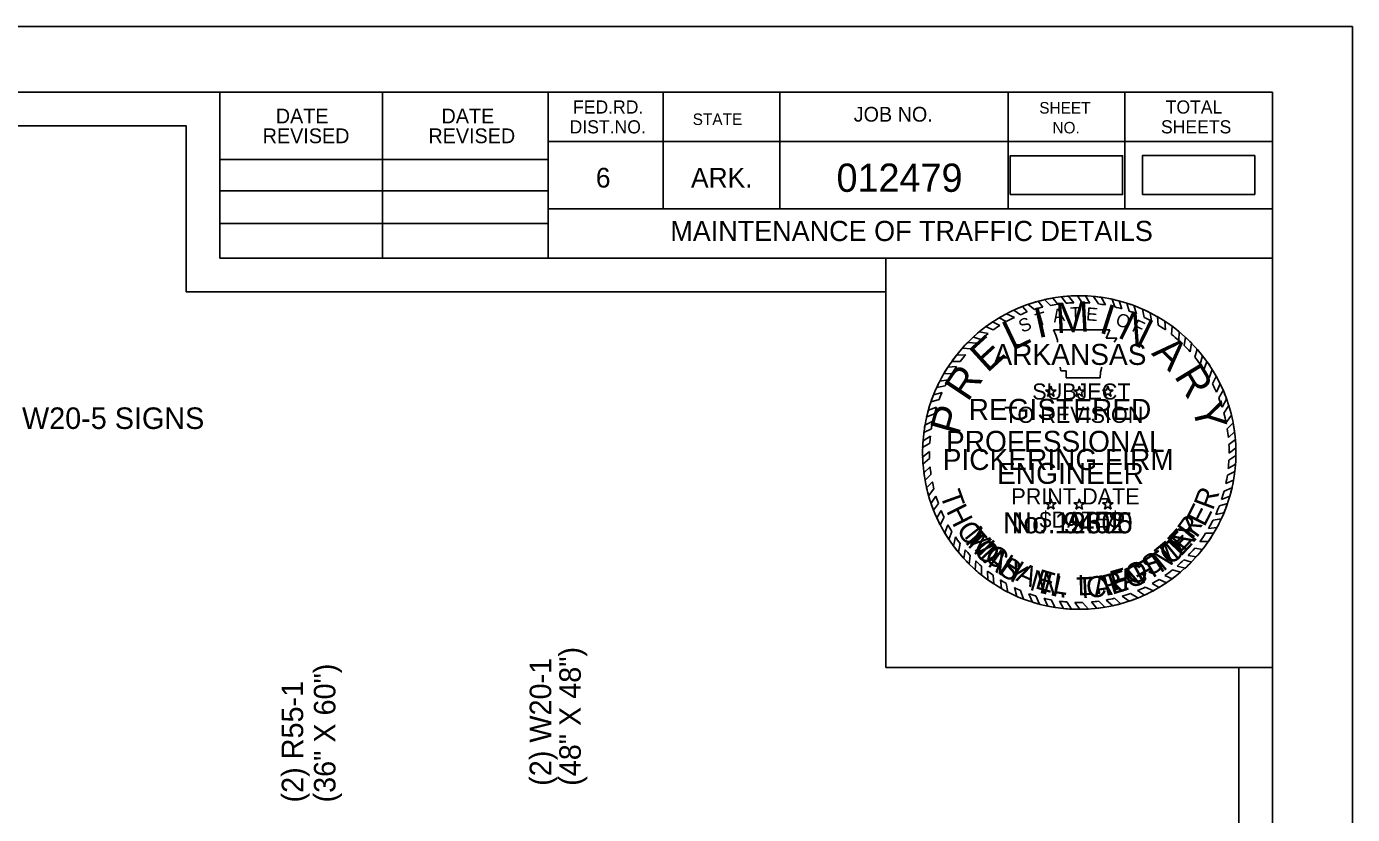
# Model space of a CAD drawing. Extents: x 1373222 to 1374279, y 380783 to 380996.
# Drawn here: x 1373476.4 to 1373555.3, y 380949.6 to 380996.5 of the extents above; entities that cross this region are included whole.
import ezdxf

# ---------------------------------------------------------------- set-up
doc = ezdxf.new("R2010")
doc.units = 0
for name, color, linetype in [('Default', 7, 'Continuous'), ('R_Border', 7, 'Continuous'), ('R_Border Notes', 7, 'Continuous'), ('R_Draft', 7, 'Continuous'), ('R_No Plot', 7, 'Continuous'), ('STAMP_PE_CRAFTON', 7, 'Continuous'), ('STAMP_PE_FOSTER', 7, 'Continuous'), ('STAMP_PE_SEAL-INFO', 7, 'Continuous'), ('STAMP_PE_TAEGTMEYER', 7, 'Continuous'), ('STAMP_PE_TXT', 7, 'Continuous'), ('STAMP_PRELIMINARY', 7, 'Continuous')]:
    doc.layers.add(name, color=color, linetype=linetype)

msp = doc.modelspace()

# ---------------------------------------------------------------- linework, layer by layer
at = {"layer": 'Default'}
for points in [[(1373534.953, 380986.497), (1373541.636, 380986.497), (1373541.636, 380988.808), (1373534.953, 380988.808)], [(1373542.823, 380986.507), (1373549.506, 380986.507), (1373549.506, 380988.818), (1373542.823, 380988.818)]]:
    msp.add_lwpolyline(points, close=True, dxfattribs=at)
at = {"layer": 'R_Border'}
for p, q in [((1373234.384, 380992.592), (1373550.564, 380992.592)), ((1373487.924, 380982.712), (1373487.924, 380992.592)), ((1373497.604, 380982.712), (1373497.604, 380992.592)), ((1373507.464, 380992.592), (1373507.464, 380982.712)), ((1373514.304, 380992.592), (1373514.304, 380985.652)), ((1373521.244, 380992.592), (1373521.244, 380985.652)), ((1373534.824, 380992.592), (1373534.824, 380985.652)), ((1373541.764, 380992.592), (1373541.764, 380985.652)), ((1373550.564, 380787.132), (1373550.564, 380992.592)), ((1373550.564, 380989.652), (1373507.464, 380989.652)), ((1373550.564, 380989.672), (1373550.564, 380989.672)), ((1373487.924, 380988.572), (1373507.464, 380988.572)), ((1373487.924, 380986.712), (1373507.464, 380986.712)), ((1373550.564, 380985.652), (1373507.464, 380985.652)), ((1373510.424, 380985.652), (1373550.564, 380985.652)), ((1373487.924, 380984.772), (1373507.464, 380984.772)), ((1373550.564, 380982.712), (1373487.924, 380982.712))]:
    msp.add_line(p, q, dxfattribs=at)
at = {"layer": 'R_No Plot'}
for points in [[(1373221.977, 380996.487), (1373555.317, 380996.487), (1373555.317, 380783.15), (1373221.977, 380783.15)], [(1373548.564, 380891.862), (1373236.384, 380891.862), (1373236.384, 380990.592), (1373485.924, 380990.592), (1373485.924, 380980.712), (1373503.464, 380980.712), (1373527.564, 380980.712), (1373527.564, 380958.38), (1373548.564, 380958.38)], [(1373236.384, 380990.592), (1373485.924, 380990.592), (1373485.924, 380980.712), (1373503.464, 380980.712), (1373527.564, 380980.712), (1373527.564, 380958.38), (1373548.564, 380958.38), (1373548.564, 380789.132), (1373236.384, 380789.132)], [(1373527.564, 380982.712), (1373550.564, 380982.712), (1373550.564, 380958.38), (1373527.564, 380958.38)]]:
    msp.add_lwpolyline(points, close=True, dxfattribs=at)
at = {"layer": 'STAMP_PE_SEAL-INFO'}
for p, q in [((1373537.485, 380980.343), (1373537.784, 380979.976)), ((1373538.001, 380980.417), (1373538.282, 380980.034)), ((1373538.736, 380980.062), (1373538.424, 380980.456)), ((1373539.234, 380980.067), (1373538.955, 380980.477)), ((1373539.692, 380980.046), (1373539.434, 380980.47)), ((1373540.198, 380979.996), (1373539.906, 380980.44)), ((1373540.624, 380979.931), (1373540.366, 380980.386)), ((1373535.168, 380979.625), (1373535.558, 380979.35)), ((1373535.676, 380979.84), (1373535.971, 380979.514)), ((1373536.024, 380979.968), (1373536.405, 380979.662)), ((1373536.615, 380980.15), (1373536.903, 380979.802)), ((1373537.003, 380980.247), (1373537.359, 380979.904)), ((1373541.186, 380979.812), (1373541.012, 380980.272)), ((1373541.587, 380979.704), (1373541.428, 380980.173)), ((1373542.039, 380979.557), (1373541.898, 380980.037)), ((1373542.458, 380979.397), (1373542.313, 380979.893)), ((1373542.919, 380979.192), (1373542.816, 380979.69)), ((1373533.903, 380978.918), (1373534.344, 380978.716)), ((1373534.289, 380979.162), (1373534.722, 380978.939)), ((1373534.737, 380979.413), (1373535.201, 380979.188)), ((1373543.365, 380978.963), (1373543.278, 380979.471)), ((1373543.752, 380978.736), (1373543.713, 380979.236)), ((1373544.187, 380978.45), (1373544.156, 380978.965)), ((1373532.762, 380978.024), (1373533.22, 380977.885)), ((1373533.105, 380978.324), (1373533.635, 380978.224)), ((1373533.482, 380978.652), (1373533.938, 380978.447)), ((1373537.537, 380978.446), (1373540.882, 380978.446)), ((1373537.659, 380978.139), (1373537.537, 380978.446)), ((1373537.763, 380977.841), (1373537.659, 380978.139)), ((1373540.882, 380978.446), (1373540.657, 380977.954)), ((1373544.547, 380978.183), (1373544.582, 380978.67)), ((1373544.994, 380977.81), (1373545.013, 380978.333)), ((1373545.306, 380977.518), (1373545.376, 380978.017)), ((1373532.103, 380977.356), (1373532.625, 380977.318)), ((1373532.426, 380977.701), (1373532.97, 380977.66)), ((1373537.77, 380977.727), (1373537.763, 380977.841)), ((1373540.657, 380977.954), (1373541.289, 380977.954)), ((1373541.289, 380977.954), (1373541.144, 380977.727)), ((1373545.665, 380977.145), (1373545.732, 380977.671)), ((1373545.939, 380976.828), (1373546.076, 380977.3)), ((1373531.48, 380976.576), (1373531.985, 380976.57)), ((1373531.758, 380976.945), (1373532.307, 380976.967)), ((1373546.263, 380976.411), (1373546.398, 380976.911)), ((1373546.483, 380976.096), (1373546.661, 380976.559)), ((1373530.999, 380975.831), (1373531.488, 380975.851)), ((1373531.245, 380976.232), (1373531.761, 380976.265)), ((1373537.961, 380976.018), (1373537.935, 380976.235)), ((1373538.275, 380976.018), (1373537.961, 380976.018)), ((1373538.275, 380975.588), (1373538.275, 380976.018)), ((1373540.321, 380975.926), (1373540.305, 380975.588)), ((1373540.399, 380976.235), (1373540.321, 380975.926)), ((1373546.791, 380975.599), (1373546.974, 380976.09)), ((1373546.991, 380975.232), (1373547.217, 380975.677)), ((1373530.58, 380975.018), (1373531.082, 380975.122)), ((1373530.768, 380975.407), (1373531.266, 380975.472)), ((1373540.305, 380975.588), (1373538.275, 380975.588)), ((1373547.222, 380974.748), (1373547.448, 380975.233)), ((1373547.362, 380974.411), (1373547.626, 380974.845)), ((1373530.246, 380974.179), (1373530.73, 380974.316)), ((1373530.396, 380974.586), (1373530.9, 380974.732)), ((1373547.557, 380973.862), (1373547.827, 380974.336)), ((1373529.985, 380973.269), (1373530.455, 380973.462)), ((1373530.089, 380973.677), (1373530.567, 380973.845)), ((1373547.665, 380973.497), (1373547.958, 380973.95)), ((1373547.798, 380972.939), (1373548.116, 380973.385)), ((1373530.263, 380972.564), (1373529.818, 380972.342)), ((1373530.349, 380973.023), (1373529.883, 380972.774)), ((1373547.867, 380972.559), (1373548.22, 380972.912)), ((1373530.168, 380971.703), (1373529.746, 380971.447)), ((1373530.204, 380972.128), (1373529.768, 380971.847)), ((1373547.933, 380972.05), (1373548.306, 380972.386)), ((1373547.965, 380971.631), (1373548.355, 380971.923)), ((1373530.151, 380971.21), (1373529.746, 380970.874)), ((1373547.967, 380970.708), (1373548.386, 380970.985)), ((1373547.978, 380971.113), (1373548.383, 380971.435)), ((1373530.158, 380970.803), (1373529.766, 380970.478)), ((1373530.191, 380970.308), (1373529.82, 380969.951)), ((1373547.927, 380970.202), (1373548.361, 380970.459)), ((1373530.243, 380969.878), (1373529.889, 380969.505)), ((1373530.322, 380969.42), (1373529.982, 380969.052)), ((1373547.786, 380969.314), (1373548.241, 380969.509)), ((1373547.876, 380969.813), (1373548.319, 380970.033)), ((1373530.415, 380969.001), (1373530.103, 380968.586)), ((1373530.539, 380968.554), (1373530.244, 380968.136)), ((1373547.531, 380968.368), (1373548.021, 380968.569)), ((1373547.678, 380968.862), (1373548.149, 380969.063)), ((1373530.68, 380968.131), (1373530.398, 380967.719)), ((1373547.396, 380967.988), (1373547.879, 380968.119)), ((1373530.846, 380967.704), (1373530.584, 380967.282)), ((1373531.018, 380967.321), (1373530.79, 380966.86)), ((1373547.021, 380967.137), (1373547.509, 380967.205)), ((1373547.182, 380967.473), (1373547.67, 380967.57)), ((1373531.253, 380966.862), (1373531.062, 380966.373)), ((1373531.488, 380966.459), (1373531.305, 380965.988)), ((1373531.691, 380966.147), (1373531.581, 380965.595)), ((1373546.577, 380966.358), (1373547.054, 380966.352)), ((1373546.749, 380966.638), (1373547.25, 380966.693)), ((1373531.972, 380965.757), (1373531.87, 380965.226)), ((1373532.276, 380965.379), (1373532.189, 380964.859)), ((1373545.93, 380965.47), (1373546.391, 380965.39)), ((1373546.238, 380965.864), (1373546.742, 380965.867)), ((1373532.578, 380965.041), (1373532.516, 380964.519)), ((1373532.901, 380964.716), (1373532.871, 380964.187)), ((1373545.292, 380964.777), (1373545.732, 380964.64)), ((1373545.546, 380965.037), (1373546.023, 380964.951)), ((1373533.245, 380964.403), (1373533.242, 380963.874)), ((1373533.605, 380964.109), (1373533.624, 380963.585)), ((1373533.943, 380963.859), (1373533.979, 380963.341)), ((1373544.154, 380963.838), (1373544.593, 380963.649)), ((1373544.615, 380964.181), (1373545.083, 380964.035)), ((1373544.886, 380964.405), (1373545.357, 380964.276)), ((1373534.37, 380963.578), (1373534.431, 380963.065)), ((1373534.721, 380963.372), (1373534.812, 380962.859)), ((1373535.202, 380963.122), (1373535.358, 380962.601)), ((1373542.988, 380963.152), (1373543.472, 380962.94)), ((1373543.396, 380963.365), (1373543.813, 380963.132)), ((1373543.811, 380963.61), (1373544.26, 380963.414)), ((1373535.574, 380962.953), (1373535.747, 380962.442)), ((1373536.067, 380962.761), (1373536.276, 380962.259)), ((1373536.476, 380962.625), (1373536.703, 380962.136)), ((1373536.984, 380962.488), (1373537.197, 380962.021)), ((1373537.382, 380962.402), (1373537.629, 380961.944)), ((1373537.882, 380962.32), (1373538.122, 380961.88)), ((1373538.319, 380962.273), (1373538.593, 380961.844)), ((1373538.803, 380962.245), (1373539.106, 380961.832)), ((1373539.263, 380962.244), (1373539.607, 380961.848)), ((1373539.782, 380962.27), (1373540.108, 380961.891)), ((1373540.22, 380962.317), (1373540.593, 380961.958)), ((1373540.665, 380962.386), (1373541.054, 380962.047)), ((1373541.158, 380962.491), (1373541.535, 380962.166)), ((1373541.617, 380962.615), (1373542.034, 380962.318)), ((1373542.11, 380962.778), (1373542.553, 380962.51)), ((1373542.529, 380962.942), (1373542.952, 380962.682))]:
    msp.add_line(p, q, dxfattribs=at)
for radius, start, end in [(9.323, 99.75254, 102.77648), (9.323, 93.93815, 96.55172), (9.323, 87.72979, 90.67067), (9.323, 81.97315, 84.82355), (9.323, 111.31242, 114.70259), (9.323, 105.23389, 109.03519), (8.914, 104.03521, 107.36155), (8.914, 98.25799, 101.03289), (8.914, 92.11016, 95.03666), (8.914, 85.96279, 88.9097), (8.914, 79.92642, 82.69597), (9.323, 75.31251, 77.94263), (8.914, 73.55748, 76.23144), (9.323, 69.60611, 72.30577), (8.914, 67.62483, 70.50398), (9.323, 63.13288, 66.2704), (9.323, 123.61993, 126.59063), (9.323, 117.65441, 120.80988), (8.914, 115.68692, 119.15827), (8.914, 110.30864, 113.16588), (8.914, 61.15575, 64.37837), (9.323, 56.90029, 60.09423), (9.323, 129.73259, 132.53764), (8.914, 127.52969, 130.96829), (8.914, 121.97456, 125.11001), (8.914, 54.92383, 58.27016), (8.914, 48.30163, 52.03953), (9.323, 50.3492, 53.71593), (9.323, 44.3405, 47.39292), (9.323, 135.40208, 138.30314), (8.914, 133.13306, 136.25623), (8.914, 42.22116, 45.55119), (9.323, 38.12472, 41.23157), (9.323, 141.60556, 144.44865), (8.914, 139.30101, 142.58729), (8.914, 36.13503, 39.53106), (9.323, 31.96138, 35.42937), (9.323, 147.00719, 149.89904), (8.914, 145.01972, 148.21036), (8.914, 29.90321, 33.66454), (9.323, 25.93909, 29.01247), (9.323, 152.86398, 155.51889), (8.914, 151.03153, 153.57304), (8.914, 23.77322, 27.22114), (9.323, 19.95381, 23.31409), (9.323, 158.40766, 161.07015), (8.914, 156.34018, 159.23194), (8.914, 17.68022, 21.42509), (9.323, 164.3068, 166.89395), (8.914, 162.43309, 165.00133), (8.914, 11.54445, 15.23639), (9.323, 13.84205, 17.44468), (9.323, 170.0003, 172.68778), (8.914, 167.90481, 170.90393), (8.914, 5.7599, 9.06056), (9.323, 7.58519, 10.86211), (9.323, 175.74093, 178.2066), (8.914, 173.73, 176.47337), (9.323, 1.72155, 4.72681), (9.323, 181.72508, 184.16255), (8.914, 179.64537, 182.26333), (8.914, 359.73289, 3.06392), (9.323, 355.71562, 358.95694), (8.914, 185.45389, 188.23401), (8.914, 353.86319, 357.12742), (9.323, 187.42037, 190.19271), (8.914, 191.22736, 193.98583), (8.914, 348.07782, 351.34355), (9.323, 349.83047, 353.08845), (9.323, 193.03695, 195.99732), (8.914, 196.96751, 199.83526), (8.914, 341.77699, 345.09248), (9.323, 343.89247, 347.03502), (9.323, 198.89671, 201.62812), (8.914, 335.6038, 339.18578), (9.323, 337.38367, 340.99332), (9.323, 204.54793, 207.43282), (8.914, 202.77613, 205.47915), (8.914, 329.55488, 333.20757), (9.323, 331.40371, 334.93315), (9.323, 210.86355, 213.65709), (8.914, 208.78826, 211.79343), (8.914, 214.18375, 217.27474), (8.914, 323.58513, 327.44069), (9.323, 325.44052, 328.98725), (9.323, 216.61154, 219.49098), (8.914, 220.39088, 223.30564), (8.914, 316.65308, 320.37109), (9.323, 318.28455, 321.80429), (9.323, 222.47995, 225.38008), (8.914, 226.24938, 229.24068), (8.914, 310.77436, 314.31605), (9.323, 312.45177, 315.66328), (9.323, 228.36648, 231.34802), (8.914, 232.22904, 234.93361), (8.914, 304.82299, 308.51428), (9.323, 306.37206, 310.20799), (9.323, 234.29502, 236.94517), (8.914, 238.22227, 240.83529), (9.323, 240.1977, 242.86128), (8.914, 244.32043, 246.94859), (8.914, 292.87452, 296.11851), (8.914, 299.07679, 302.17235), (9.323, 300.62101, 303.87026), (9.323, 246.57598, 249.15579), (8.914, 250.34912, 253.12157), (9.323, 252.59667, 255.32518), (8.914, 256.50505, 259.11916), (8.914, 262.37828, 265.20115), (8.914, 268.3215, 271.27698), (8.914, 274.61565, 277.44863), (8.914, 280.34588, 283.58137), (8.914, 286.64233, 289.97826), (9.323, 288.57086, 291.97334), (9.323, 294.64808, 298.21662), (9.323, 258.44328, 261.13983), (9.323, 264.19784, 267.10092), (9.323, 270.25484, 273.33609), (9.323, 276.42389, 279.43574), (9.323, 282.31994, 285.37019)]:
    msp.add_arc((1373539.064, 380971.155), radius, start, end, dxfattribs=at)
at = {"layer": 'STAMP_PE_TXT'}
for p, q in [((1373537.244, 380974.726), (1373537.046, 380974.871)), ((1373537.046, 380974.871), (1373537.291, 380974.871)), ((1373537.291, 380974.871), (1373537.366, 380975.104)), ((1373537.366, 380975.104), (1373537.442, 380974.871)), ((1373537.442, 380974.871), (1373537.687, 380974.871)), ((1373537.687, 380974.871), (1373537.489, 380974.726)), ((1373538.942, 380974.726), (1373538.743, 380974.871)), ((1373538.743, 380974.871), (1373538.989, 380974.871)), ((1373538.989, 380974.871), (1373539.064, 380975.104)), ((1373539.064, 380975.104), (1373539.14, 380974.871)), ((1373539.14, 380974.871), (1373539.385, 380974.871)), ((1373539.385, 380974.871), (1373539.187, 380974.726)), ((1373540.64, 380974.726), (1373540.441, 380974.871)), ((1373540.441, 380974.871), (1373540.687, 380974.871)), ((1373540.687, 380974.871), (1373540.762, 380975.104)), ((1373540.762, 380975.104), (1373540.838, 380974.871)), ((1373540.838, 380974.871), (1373541.083, 380974.871)), ((1373541.083, 380974.871), (1373540.885, 380974.726)), ((1373537.168, 380974.493), (1373537.244, 380974.726)), ((1373537.366, 380974.637), (1373537.168, 380974.493)), ((1373537.565, 380974.493), (1373537.366, 380974.637)), ((1373537.489, 380974.726), (1373537.565, 380974.493)), ((1373538.866, 380974.493), (1373538.942, 380974.726)), ((1373539.064, 380974.637), (1373538.866, 380974.493)), ((1373539.263, 380974.493), (1373539.064, 380974.637)), ((1373539.187, 380974.726), (1373539.263, 380974.493)), ((1373540.564, 380974.493), (1373540.64, 380974.726)), ((1373540.762, 380974.637), (1373540.564, 380974.493)), ((1373540.961, 380974.493), (1373540.762, 380974.637)), ((1373540.885, 380974.726), (1373540.961, 380974.493)), ((1373537.244, 380968.019), (1373537.046, 380968.164)), ((1373537.046, 380968.164), (1373537.291, 380968.164)), ((1373537.168, 380967.786), (1373537.244, 380968.019)), ((1373537.366, 380967.93), (1373537.168, 380967.786)), ((1373537.291, 380968.164), (1373537.366, 380968.397)), ((1373537.366, 380968.397), (1373537.442, 380968.164)), ((1373537.565, 380967.786), (1373537.366, 380967.93)), ((1373537.442, 380968.164), (1373537.687, 380968.164)), ((1373537.687, 380968.164), (1373537.489, 380968.019)), ((1373537.489, 380968.019), (1373537.565, 380967.786)), ((1373538.942, 380968.019), (1373538.743, 380968.164)), ((1373538.743, 380968.164), (1373538.989, 380968.164)), ((1373538.866, 380967.786), (1373538.942, 380968.019)), ((1373539.064, 380967.93), (1373538.866, 380967.786)), ((1373538.989, 380968.164), (1373539.064, 380968.397)), ((1373539.064, 380968.397), (1373539.14, 380968.164)), ((1373539.263, 380967.786), (1373539.064, 380967.93)), ((1373539.14, 380968.164), (1373539.385, 380968.164)), ((1373539.385, 380968.164), (1373539.187, 380968.019)), ((1373539.187, 380968.019), (1373539.263, 380967.786)), ((1373540.64, 380968.019), (1373540.441, 380968.164)), ((1373540.441, 380968.164), (1373540.687, 380968.164)), ((1373540.564, 380967.786), (1373540.64, 380968.019)), ((1373540.762, 380967.93), (1373540.564, 380967.786)), ((1373540.687, 380968.164), (1373540.762, 380968.397)), ((1373540.762, 380968.397), (1373540.838, 380968.164)), ((1373540.961, 380967.786), (1373540.762, 380967.93)), ((1373540.838, 380968.164), (1373541.083, 380968.164)), ((1373541.083, 380968.164), (1373540.885, 380968.019)), ((1373540.885, 380968.019), (1373540.961, 380967.786))]:
    msp.add_line(p, q, dxfattribs=at)
at = {"layer": 'STAMP_PRELIMINARY'}
msp.add_circle((1373539.064, 380971.155), 9.323, dxfattribs=at)

# ---------------------------------------------------------------- texts
at = {"layer": 'R_Border'}
for s, height, p in [('DATE', 0.8792, (1373491.262, 380990.729)), ('DATE', 0.8792, (1373501.122, 380990.729)), ('FED.RD.', 0.7819, (1373508.944, 380991.312)), ('JOB NO.', 0.8792, (1373525.644, 380990.832)), ('SHEET', 0.684, (1373536.684, 380991.312)), ('TOTAL', 0.7819, (1373544.204, 380991.312)), ('DIST.NO.', 0.7819, (1373508.744, 380990.132)), ('STATE', 0.684, (1373516.064, 380990.632)), ('NO.', 0.684, (1373537.464, 380990.132)), ('SHEETS', 0.7819, (1373543.924, 380990.132)), ('REVISED', 0.8792, (1373490.482, 380989.549)), ('REVISED', 0.8792, (1373500.342, 380989.549)), ('6', 1.172, (1373510.304, 380986.912)), ('ARK.', 1.1723, (1373515.964, 380986.912))]:
    msp.add_text(s, height=height, dxfattribs=at).set_placement(p)
at = {"layer": 'R_Border Notes'}
for s, height, p in [('012479', 1.68, (1373524.622, 380986.658)), ('MAINTENANCE OF TRAFFIC DETAILS', 1.2, (1373514.733, 380983.731))]:
    msp.add_text(s, height=height, dxfattribs=at).set_placement(p)
at = {"layer": 'R_Draft'}
msp.add_text('TO BE REPLACED AS NEEDED BY EQUIVALENT W20-5 SIGNS', height=1.28, dxfattribs=at).set_placement((1373436.406, 380972.557))
for s, height, rotation, p in [('(48" X 48")', 1.28, 90, (1373509.407, 380951.338)), ('(36" X 60")', 1.28016, 90.05011, (1373494.814, 380950.348)), ('(2) W20-1', 1.28, 90, (1373507.647, 380951.338)), ('(2) R55-1', 1.2802, 90.05011, (1373492.894, 380950.347))]:
    msp.add_text(s, height=height, rotation=rotation, dxfattribs=at).set_placement(p)
at = {"layer": 'STAMP_PE_CRAFTON'}
msp.add_text('No. 12370', height=1.25, dxfattribs=at).set_placement((1373534.526, 380966.352))
for s, rotation, p in [('T', 310.74416, (1373532.03, 380966.053)), ('N', 49.24107, (1373545.347, 380965.177)), ('O', 317.64216, (1373532.698, 380965.242)), ('N', 324.45371, (1373533.544, 380964.457)), ('T', 34.11362, (1373543.641, 380963.794)), ('O', 41.83906, (1373544.499, 380964.396)), ('Y', 331.16864, (1373534.577, 380963.74)), ('F', 28.78207, (1373542.726, 380963.284)), ('N', 347.47515, (1373536.631, 380962.824)), ('C', 6.01169, (1373539.536, 380962.496)), ('R', 14.81888, (1373540.632, 380962.611)), ('A', 20.51248, (1373541.745, 380962.911)), ('.', 356.89262, (1373537.86, 380962.547))]:
    msp.add_text(s, height=1.25, rotation=rotation, dxfattribs=at).set_placement(p)
at = {"layer": 'STAMP_PE_FOSTER'}
msp.add_text('No. 9402', height=1.25, dxfattribs=at).set_placement((1373535.05, 380966.352))
for s, rotation, p in [('R', 54.5031, (1373545.789, 380965.966)), ('M', 308.33902, (1373532.18, 380966.177)), ('E', 46.96131, (1373545.065, 380965.145)), ('I', 314.18423, (1373532.978, 380965.24)), ('C', 319.87327, (1373533.332, 380964.886)), ('T', 39.41938, (1373544.207, 380964.395)), ('H', 327.72349, (1373534.262, 380964.15)), ('O', 23.71897, (1373542.144, 380963.237)), ('S', 31.72336, (1373543.255, 380963.767)), ('A', 335.72761, (1373535.242, 380963.568)), ('E', 343.5779, (1373536.38, 380963.098)), ('L', 350.81148, (1373537.438, 380962.82)), ('L', 1.26658, (1373538.978, 380962.664)), ('F', 15.86908, (1373541.099, 380962.91)), ('.', 6.80354, (1373540.025, 380962.722))]:
    msp.add_text(s, height=1.2, rotation=rotation, dxfattribs=at).set_placement(p)
at = {"layer": 'STAMP_PE_TAEGTMEYER'}
for s, rotation, p in [('T', 289.64597, (1373530.759, 380968.665)), ('R', 69.57001, (1373547.01, 380967.67)), ('H', 296.73386, (1373531.119, 380967.681)), ('E', 63.0984, (1373546.511, 380966.688)), ('O', 303.77078, (1373531.712, 380966.573)), ('Y', 53.99864, (1373545.842, 380965.747)), ('M', 314.20329, (1373532.367, 380965.622)), ('E', 46.80938, (1373545.103, 380964.932)), ('M', 39.30005, (1373544.062, 380964.053)), ('A', 321.0594, (1373533.328, 380964.657)), ('S', 327.82385, (1373534.154, 380964.013)), ('T', 31.46601, (1373543.164, 380963.51)), ('N', 344.27273, (1373536.051, 380963.007)), ('T', 3.00609, (1373538.929, 380962.476)), ('A', 8.98261, (1373539.975, 380962.531)), ('E', 17.68363, (1373541.014, 380962.686)), ('G', 23.30524, (1373542.064, 380963.017)), ('.', 350.64643, (1373537.264, 380962.675))]:
    msp.add_text(s, height=1.25, rotation=rotation, dxfattribs=at).set_placement(p)
msp.add_text('No. 19605', height=1.25, dxfattribs=at).set_placement((1373534.526, 380966.352))
at = {"layer": 'STAMP_PE_TXT'}
for s, rotation, p in [('T', 16.311, (1373536.586, 380978.631)), ('A', 9.0679, (1373537.548, 380978.884)), ('T', 1.82479, (1373538.535, 380979.013)), ('E', 355.20019, (1373539.445, 380979.022)), ('S', 23.5541, (1373535.663, 380978.259)), ('O', 342.25065, (1373541.172, 380978.745)), ('F', 335.00755, (1373542.137, 380978.407))]:
    msp.add_text(s, height=0.781, rotation=rotation, dxfattribs=at).set_placement(p)
for s, p in [('ARKANSAS', (1373533.957, 380976.365)), ('REGISTERED', (1373532.481, 380973.096)), ('PROFESSIONAL', (1373531.133, 380971.195)), ('ENGINEER', (1373534.173, 380969.293))]:
    msp.add_text(s, height=1.25, dxfattribs=at).set_placement(p)
at = {"layer": 'STAMP_PRELIMINARY'}
for s, rotation, p in [('I', 12.52485, (1373536.602, 380977.942)), ('M', 3.10738, (1373537.7, 380978.251)), ('I', 342.31637, (1373540.168, 380978.318)), ('N', 333.9382, (1373541.275, 380978.044)), ('L', 25.51305, (1373535.073, 380977.182)), ('E', 42.35784, (1373533.591, 380975.851)), ('A', 315.65789, (1373543.309, 380977.019)), ('R', 301.38306, (1373544.677, 380975.705)), ('R', 56.22922, (1373532.435, 380974.119)), ('Y', 283.25926, (1373545.766, 380973.918)), ('P', 73.91301, (1373531.886, 380972.095))]:
    msp.add_text(s, height=1.8, rotation=rotation, dxfattribs=at).set_placement(p)
for s, height, p in [('SUBJECT', 0.96, (1373536.264, 380974.304)), ('TO REVISION', 0.96, (1373534.6, 380972.92)), ('PICKERING FIRM', 1.25, (1373530.938, 380970.118)), ('PRINT DATE', 0.96, (1373535.022, 380968.07)), ('$DATE$', 0.96, (1373536.699, 380966.686))]:
    msp.add_text(s, height=height, dxfattribs=at).set_placement(p)

doc.saveas('drawing.dxf')
